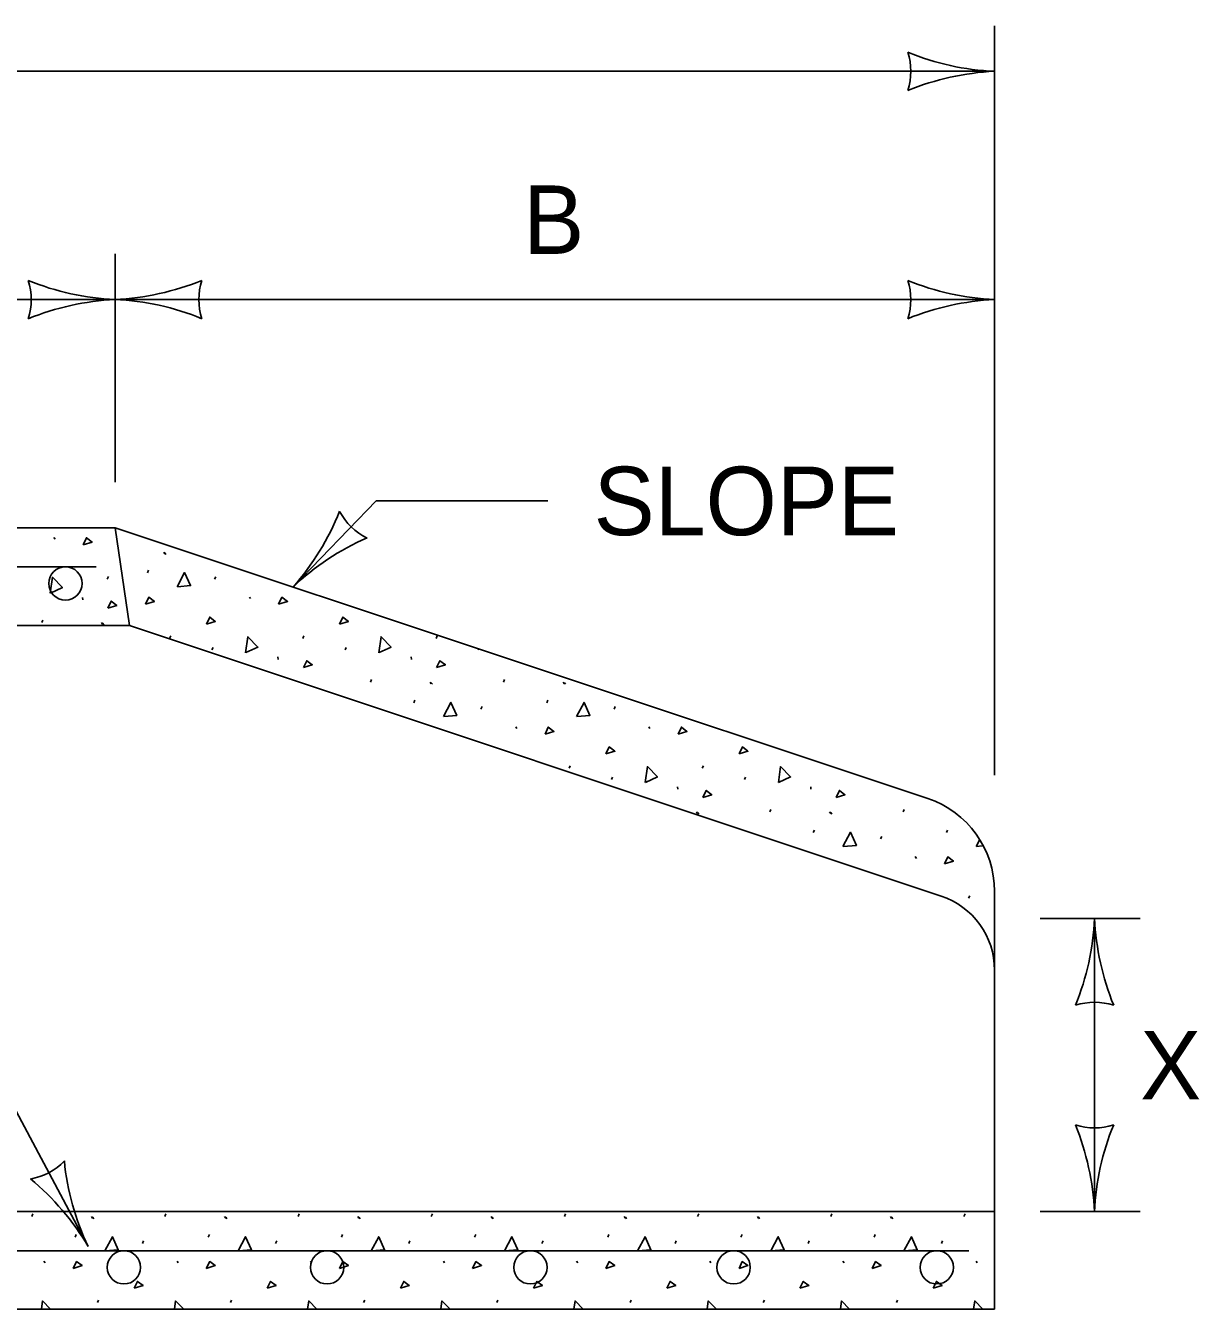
# Model space of a CAD drawing. Extents: x 49991.4 to 50022.1, y 49985 to 50011.4.
# Drawn here: x 50001.918 to 50002.946, y 49995.4 to 49996.525 of the extents above; entities that cross this region are included whole.
import ezdxf

# ---------------------------------------------------------------- set-up
doc = ezdxf.new("R2010")
doc.units = 0
for name, color, linetype in [('Level 1', 7, 'Continuous'), ('Level 2', 7, 'Continuous'), ('Level 3', 7, 'Continuous')]:
    doc.layers.add(name, color=color, linetype=linetype)

msp = doc.modelspace()

# ---------------------------------------------------------------- linework, layer by layer
at = {"layer": 'Level 1'}
for p, q in [((50000.6836, 49996.0847), (50001.9962, 49996.0847)), ((50001.9962, 49996.0847), (50002.7082, 49995.8474)), ((50001.9962, 49996.0847), (50002.0087, 49995.999)), ((50001.9962, 49996.0847), (50002.0087, 49995.999)), ((50002.0087, 49995.999), (50001.9962, 49996.0847)), ((50001.9962, 49996.0847), (50002.7082, 49995.8474)), ((50001.9962, 49996.0847), (50002.0087, 49995.999)), ((50001.9426, 49996.0761), (50001.9436, 49996.0747)), ((50002.0389, 49996.0633), (50002.0398, 49996.0618)), ((50002.0398, 49996.0627), (50002.0408, 49996.0613)), ((50002.0245, 49996.0452), (50002.0255, 49996.0474)), ((50001.9894, 49996.0398), (50001.9904, 49996.042)), ((50002.0834, 49996.0396), (50002.0844, 49996.0418)), ((50001.9677, 49996.0237), (50001.9679, 49996.0215)), ((50002.1139, 49996.024), (50002.1149, 49996.0226)), ((50001.9319, 49996.0016), (50001.9329, 49996.0038)), ((50001.9843, 49996.0016), (50001.9853, 49996.0001)), ((50001.9853, 49996.001), (50001.9862, 49995.9996)), ((50002.0087, 49995.999), (50000.7692, 49995.999)), ((50002.72, 49995.762), (50002.0087, 49995.9992)), ((50002.0087, 49995.9992), (50002.0087, 49995.999)), ((50002.72, 49995.762), (50002.0087, 49995.9992)), ((50002.044, 49995.9877), (50002.045, 49995.9899)), ((50002.1607, 49995.9877), (50002.1616, 49995.9899)), ((50002.2774, 49995.9877), (50002.2783, 49995.9899)), ((50002.081, 49995.9777), (50002.082, 49995.9799)), ((50002.1977, 49995.9777), (50002.1987, 49995.9799)), ((50002.3144, 49995.9777), (50002.3148, 49995.9785)), ((50002.1389, 49995.9716), (50002.1392, 49995.9694)), ((50002.2556, 49995.9716), (50002.2559, 49995.9694)), ((50002.2199, 49995.9495), (50002.2208, 49995.9517)), ((50002.2722, 49995.9495), (50002.2732, 49995.948)), ((50002.2732, 49995.9489), (50002.2742, 49995.9475)), ((50002.3366, 49995.9495), (50002.3375, 49995.9517)), ((50002.3889, 49995.9495), (50002.3899, 49995.948)), ((50002.3899, 49995.9489), (50002.3909, 49995.9475)), ((50002.2579, 49995.9314), (50002.2588, 49995.9336)), ((50002.3746, 49995.9314), (50002.3755, 49995.9336)), ((50002.3168, 49995.9258), (50002.3178, 49995.928)), ((50002.4335, 49995.9258), (50002.4345, 49995.928)), ((50002.3473, 49995.9102), (50002.3483, 49995.9088)), ((50002.464, 49995.9102), (50002.4649, 49995.9088)), ((50002.3941, 49995.8739), (50002.395, 49995.8761)), ((50002.4311, 49995.864), (50002.4321, 49995.8661)), ((50002.5107, 49995.8739), (50002.5117, 49995.8761)), ((50002.5478, 49995.864), (50002.5487, 49995.8661)), ((50002.6274, 49995.8739), (50002.6276, 49995.8743)), ((50002.489, 49995.8578), (50002.4892, 49995.8556)), ((50002.6057, 49995.8578), (50002.6059, 49995.8556)), ((50002.5056, 49995.8357), (50002.5066, 49995.8342)), ((50002.5066, 49995.8351), (50002.5076, 49995.8337)), ((50002.5699, 49995.8357), (50002.5709, 49995.8379)), ((50002.6223, 49995.8357), (50002.6233, 49995.8342)), ((50002.6233, 49995.8351), (50002.6243, 49995.8337)), ((50002.6866, 49995.8357), (50002.6876, 49995.8379)), ((50002.6079, 49995.8176), (50002.6089, 49995.8198)), ((50002.6669, 49995.812), (50002.6679, 49995.8142)), ((50002.7246, 49995.8176), (50002.7256, 49995.8198)), ((50002.6973, 49995.7965), (50002.6983, 49995.795)), ((50002.7668, 49995.3998), (50002.7668, 49995.7662)), ((50002.7668, 49995.4854), (50002.7668, 49995.7662)), ((50002.7668, 49995.7662), (50002.7668, 49995.3998)), ((50002.7668, 49995.3998), (50002.7668, 49995.7662)), ((50002.7441, 49995.7602), (50002.7451, 49995.7623)), ((50002.7464, 49995.7465), (50002.7471, 49995.7455)), ((50000.7692, 49995.4854), (50002.7668, 49995.4854)), ((50001.9232, 49995.4812), (50001.9241, 49995.4834)), ((50002.0398, 49995.4812), (50002.0408, 49995.4834)), ((50002.1565, 49995.4812), (50002.1575, 49995.4834)), ((50002.2732, 49995.4812), (50002.2742, 49995.4834)), ((50002.3899, 49995.4812), (50002.3909, 49995.4834)), ((50002.5066, 49995.4812), (50002.5076, 49995.4834)), ((50002.6233, 49995.4812), (50002.6243, 49995.4834)), ((50002.74, 49995.4812), (50002.741, 49995.4834)), ((50002.7668, 49995.4854), (50002.7668, 49995.3998)), ((50001.9755, 49995.4812), (50001.9765, 49995.4797)), ((50001.9765, 49995.4806), (50001.9775, 49995.4792)), ((50002.0922, 49995.4812), (50002.0932, 49995.4797)), ((50002.0932, 49995.4806), (50002.0942, 49995.4792)), ((50002.2089, 49995.4812), (50002.2099, 49995.4797)), ((50002.2099, 49995.4806), (50002.2109, 49995.4792)), ((50002.3256, 49995.4812), (50002.3266, 49995.4797)), ((50002.3266, 49995.4806), (50002.3276, 49995.4792)), ((50002.4423, 49995.4812), (50002.4433, 49995.4797)), ((50002.4433, 49995.4806), (50002.4442, 49995.4792)), ((50002.559, 49995.4812), (50002.56, 49995.4797)), ((50002.56, 49995.4806), (50002.5609, 49995.4792)), ((50002.6757, 49995.4812), (50002.6766, 49995.4797)), ((50002.6766, 49995.4806), (50002.6776, 49995.4792)), ((50001.9612, 49995.4631), (50001.9621, 49995.4653)), ((50002.0779, 49995.4631), (50002.0788, 49995.4653)), ((50002.1945, 49995.4631), (50002.1955, 49995.4653)), ((50002.3112, 49995.4631), (50002.3122, 49995.4653)), ((50002.4279, 49995.4631), (50002.4289, 49995.4653)), ((50002.5446, 49995.4631), (50002.5456, 49995.4653)), ((50002.6613, 49995.4631), (50002.6623, 49995.4653)), ((50002.0201, 49995.4575), (50002.0211, 49995.4597)), ((50002.1368, 49995.4575), (50002.1378, 49995.4597)), ((50002.2535, 49995.4575), (50002.2545, 49995.4597)), ((50002.3702, 49995.4575), (50002.3712, 49995.4597)), ((50002.4869, 49995.4575), (50002.4878, 49995.4597)), ((50002.6036, 49995.4575), (50002.6045, 49995.4597)), ((50002.7203, 49995.4575), (50002.7212, 49995.4597)), ((50001.9339, 49995.442), (50001.9349, 49995.4405)), ((50002.0506, 49995.442), (50002.0515, 49995.4405)), ((50002.1673, 49995.442), (50002.1682, 49995.4405)), ((50002.2839, 49995.442), (50002.2849, 49995.4405)), ((50002.4006, 49995.442), (50002.4016, 49995.4405)), ((50002.5173, 49995.442), (50002.5183, 49995.4405)), ((50002.634, 49995.442), (50002.635, 49995.4405)), ((50002.7507, 49995.442), (50002.7517, 49995.4405)), ((50001.9807, 49995.4057), (50001.9816, 49995.4078)), ((50002.0973, 49995.4057), (50002.0983, 49995.4078)), ((50002.214, 49995.4057), (50002.215, 49995.4078)), ((50002.3307, 49995.4057), (50002.3317, 49995.4078)), ((50002.4474, 49995.4057), (50002.4484, 49995.4078)), ((50002.5641, 49995.4057), (50002.5651, 49995.4078)), ((50002.6808, 49995.4057), (50002.6818, 49995.4078)), ((50000.6836, 49995.3998), (50002.7668, 49995.3998)), ((50000.6836, 49995.3998), (50002.7668, 49995.3998)), ((50002.7668, 49995.3998), (50000.6836, 49995.3998)), ((50002.7668, 49995.3998), (50000.6836, 49995.3998)), ((50002.7668, 49995.3998), (50000.6836, 49995.3998)), ((50002.7668, 49995.3998), (50000.6836, 49995.3998)), ((50002.76, 49995.3998), (50002.7601, 49995.4))]:
    msp.add_line(p, q, dxfattribs=at)
for points in [[(50001.9682, 49996.0698), (50001.9711, 49996.0759), (50001.976, 49996.0722), (50001.9682, 49996.0698)], [(50000.7828, 49996.0504), (50001.9796, 49996.0504)], [(50001.9394, 49996.0273), (50001.9413, 49996.0413), (50001.95, 49996.0323), (50001.9396, 49996.0274)], [(50002.0506, 49996.033), (50002.0571, 49996.0455), (50002.0623, 49996.034), (50002.0508, 49996.033)], [(50002.0228, 49996.0177), (50002.0257, 49996.0238), (50002.0306, 49996.0201), (50002.0228, 49996.0177)], [(50002.1395, 49996.0177), (50002.1424, 49996.0238), (50002.1473, 49996.0201), (50002.1395, 49996.0177)], [(50001.9899, 49996.0143), (50001.9928, 49996.0204), (50001.9977, 49996.0167), (50001.9899, 49996.0143)], [(50002.0762, 49996.0003), (50002.0791, 49996.0064), (50002.084, 49996.0027), (50002.0762, 49996.0003)], [(50002.1929, 49996.0003), (50002.1958, 49996.0064), (50002.2007, 49996.0027), (50002.1929, 49996.0003)], [(50002.1106, 49995.9752), (50002.1126, 49995.9892), (50002.1213, 49995.9801), (50002.1109, 49995.9753)], [(50002.2273, 49995.9752), (50002.2293, 49995.9892), (50002.238, 49995.9801), (50002.2276, 49995.9753)], [(50002.1612, 49995.9622), (50002.1641, 49995.9682), (50002.169, 49995.9646), (50002.1612, 49995.9622)], [(50002.2779, 49995.9622), (50002.2808, 49995.9682), (50002.2856, 49995.9646), (50002.2779, 49995.9622)], [(50002.2839, 49995.9193), (50002.2905, 49995.9317), (50002.2956, 49995.9202), (50002.2842, 49995.9193)], [(50002.4006, 49995.9193), (50002.4072, 49995.9317), (50002.4123, 49995.9202), (50002.4009, 49995.9193)], [(50002.3729, 49995.9039), (50002.3758, 49995.91), (50002.3807, 49995.9063), (50002.3729, 49995.9039)], [(50002.4895, 49995.9039), (50002.4925, 49995.91), (50002.4973, 49995.9063), (50002.4895, 49995.9039)], [(50002.4263, 49995.8865), (50002.4292, 49995.8926), (50002.4341, 49995.8889), (50002.4263, 49995.8865)], [(50002.5429, 49995.8865), (50002.5459, 49995.8926), (50002.5507, 49995.8889), (50002.5429, 49995.8865)], [(50002.4607, 49995.8614), (50002.4626, 49995.8754), (50002.4714, 49995.8664), (50002.4609, 49995.8615)], [(50002.5774, 49995.8614), (50002.5793, 49995.8754), (50002.5881, 49995.8664), (50002.5776, 49995.8615)], [(50002.5112, 49995.8484), (50002.5142, 49995.8545), (50002.519, 49995.8508), (50002.5112, 49995.8484)], [(50002.6279, 49995.8484), (50002.6308, 49995.8545), (50002.6357, 49995.8508), (50002.6279, 49995.8484)], [(50002.634, 49995.8055), (50002.6406, 49995.8179), (50002.6457, 49995.8064), (50002.6343, 49995.8055)], [(50002.7507, 49995.8055), (50002.7536, 49995.811)], [(50002.7559, 49995.8059), (50002.7509, 49995.8055)], [(50002.7229, 49995.7901), (50002.7258, 49995.7962), (50002.7307, 49995.7926), (50002.7229, 49995.7901)], [(50001.9872, 49995.451), (50001.9938, 49995.4634), (50001.9989, 49995.4519), (50001.9875, 49995.451)], [(50002.1039, 49995.451), (50002.1105, 49995.4634), (50002.1156, 49995.4519), (50002.1042, 49995.451)], [(50002.2206, 49995.451), (50002.2272, 49995.4634), (50002.2323, 49995.4519), (50002.2209, 49995.451)], [(50002.3373, 49995.451), (50002.3439, 49995.4634), (50002.349, 49995.4519), (50002.3375, 49995.451)], [(50002.454, 49995.451), (50002.4606, 49995.4634), (50002.4657, 49995.4519), (50002.4542, 49995.451)], [(50002.5707, 49995.451), (50002.5773, 49995.4634), (50002.5824, 49995.4519), (50002.5709, 49995.451)], [(50002.6874, 49995.451), (50002.6939, 49995.4634), (50002.6991, 49995.4519), (50002.6876, 49995.451)], [(50000.7853, 49995.4512), (50002.7442, 49995.4512)], [(50001.9595, 49995.4356), (50001.9624, 49995.4417), (50001.9673, 49995.4381), (50001.9595, 49995.4356)], [(50002.0761, 49995.4356), (50002.0791, 49995.4417), (50002.0839, 49995.4381), (50002.0761, 49995.4356)], [(50002.1928, 49995.4356), (50002.1958, 49995.4417), (50002.2006, 49995.4381), (50002.1928, 49995.4356)], [(50002.3095, 49995.4356), (50002.3124, 49995.4417), (50002.3173, 49995.4381), (50002.3095, 49995.4356)], [(50002.4262, 49995.4356), (50002.4291, 49995.4417), (50002.434, 49995.4381), (50002.4262, 49995.4356)], [(50002.5429, 49995.4356), (50002.5458, 49995.4417), (50002.5507, 49995.4381), (50002.5429, 49995.4356)], [(50002.6596, 49995.4356), (50002.6625, 49995.4417), (50002.6674, 49995.4381), (50002.6596, 49995.4356)], [(50002.0129, 49995.4182), (50002.0158, 49995.4243), (50002.0207, 49995.4206), (50002.0129, 49995.4182)], [(50002.1295, 49995.4182), (50002.1325, 49995.4243), (50002.1373, 49995.4206), (50002.1295, 49995.4182)], [(50002.2462, 49995.4182), (50002.2492, 49995.4243), (50002.254, 49995.4206), (50002.2462, 49995.4182)], [(50002.3629, 49995.4182), (50002.3658, 49995.4243), (50002.3707, 49995.4206), (50002.3629, 49995.4182)], [(50002.4796, 49995.4182), (50002.4825, 49995.4243), (50002.4874, 49995.4206), (50002.4796, 49995.4182)], [(50002.5963, 49995.4182), (50002.5992, 49995.4243), (50002.6041, 49995.4206), (50002.5963, 49995.4182)], [(50002.713, 49995.4182), (50002.7159, 49995.4243), (50002.7208, 49995.4206), (50002.713, 49995.4182)], [(50001.9316, 49995.3998), (50001.9326, 49995.4071), (50001.9397, 49995.3998)], [(50002.0482, 49995.3998), (50002.0492, 49995.4071), (50002.0563, 49995.3998)], [(50002.1649, 49995.3998), (50002.1659, 49995.4071), (50002.173, 49995.3998)], [(50002.2816, 49995.3998), (50002.2826, 49995.4071), (50002.2897, 49995.3998)], [(50002.3983, 49995.3998), (50002.3993, 49995.4071), (50002.4064, 49995.3998)], [(50002.515, 49995.3998), (50002.516, 49995.4071), (50002.5231, 49995.3998)], [(50002.6317, 49995.3998), (50002.6327, 49995.4071), (50002.6398, 49995.3998)], [(50002.7484, 49995.3998), (50002.7494, 49995.4071), (50002.7565, 49995.3998)]]:
    msp.add_lwpolyline(points, dxfattribs=at)
for centre in [(50001.9527, 49996.0359), (50002.0039, 49995.4366), (50002.182, 49995.4366), (50002.3601, 49995.4366), (50002.5382, 49995.4366), (50002.7162, 49995.4366)]:
    msp.add_circle(centre, 0.0146, dxfattribs=at)
for centre, radius, end in [((50002.6812, 49995.7662), 0.0856, 71.5726), ((50002.6812, 49995.7662), 0.0856, 71.5726), ((50002.6983, 49995.697), 0.0685, 71.5723), ((50002.6983, 49995.697), 0.0685, 71.5723)]:
    msp.add_arc(centre, radius, 0, end, dxfattribs=at)
at = {"layer": 'Level 3'}
for p, q in [((50002.7668, 49996.5247), (50002.7668, 49996.0522)), ((50000.6836, 49996.4847), (50002.7668, 49996.4847)), ((50001.9962, 49996.3247), (50001.9962, 49996.1247)), ((50000.6836, 49996.2847), (50001.9962, 49996.2847)), ((50001.9962, 49996.2847), (50002.7668, 49996.2847)), ((50002.225, 49996.1082), (50002.1521, 49996.0328)), ((50002.3755, 49996.1082), (50002.225, 49996.1082)), ((50002.7668, 49996.0522), (50002.7668, 49995.8679)), ((50002.8068, 49995.7423), (50002.8944, 49995.7423)), ((50002.8544, 49995.4854), (50002.8544, 49995.7423)), ((50001.8874, 49995.6147), (50001.9727, 49995.4548)), ((50002.8068, 49995.4854), (50002.8944, 49995.4854))]:
    msp.add_line(p, q, dxfattribs=at)
for centre, radius, start, end in [((50002.776, 49996.7068), 0.2223, 247.456, 267.6395), ((50002.6386, 49996.4847), 0.0548, 342.1388, 17.8612), ((50002.7783, 49996.252), 0.233, 92.8273, 112.0772), ((50002.0054, 49996.5068), 0.2223, 247.456, 267.6395), ((50001.868, 49996.2847), 0.0548, 342.1388, 17.8612), ((50001.9847, 49996.5174), 0.233, 272.8273, 292.0772), ((50002.1244, 49996.2847), 0.0548, 162.1388, 197.8612), ((50002.776, 49996.5068), 0.2223, 247.456, 267.6395), ((50002.6386, 49996.2847), 0.0548, 342.1388, 17.8612), ((50002.0077, 49996.052), 0.233, 92.8273, 112.0772), ((50001.987, 49996.0626), 0.2223, 67.456, 87.6395), ((50002.7783, 49996.052), 0.233, 92.8273, 112.0772), ((50001.9768, 49996.1862), 0.233, 318.801, 338.0508), ((50002.2412, 49996.1249), 0.0548, 208.1125, 243.8348), ((50002.3054, 49995.8718), 0.2223, 113.4297, 133.6132), ((50002.6323, 49995.7515), 0.2223, 337.456, 357.6395), ((50003.0871, 49995.7538), 0.233, 182.8273, 202.0772), ((50002.8544, 49995.6141), 0.0548, 72.1388, 107.8612), ((50002.8544, 49995.6136), 0.0548, 252.1388, 287.8612), ((50002.6217, 49995.4739), 0.233, 2.8273, 22.0772), ((50003.0765, 49995.4762), 0.2223, 157.456, 177.6395), ((50001.9124, 49995.5679), 0.0548, 280.2056, 315.928), ((50002.173, 49995.5512), 0.2223, 185.5228, 205.7063), ((50001.7728, 49995.3352), 0.233, 30.8941, 50.144)]:
    msp.add_arc(centre, radius, start, end, dxfattribs=at)

# ---------------------------------------------------------------- texts
at = {"layer": 'Level 2'}
for s, p in [('B', (50002.3538, 49996.3247)), ('SLOPE', (50002.4155, 49996.0782)), ('X', (50002.8944, 49995.5838))]:
    msp.add_text(s, height=0.06, dxfattribs=at).set_placement(p)

doc.saveas('drawing.dxf')
